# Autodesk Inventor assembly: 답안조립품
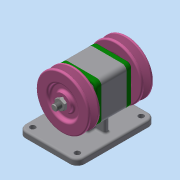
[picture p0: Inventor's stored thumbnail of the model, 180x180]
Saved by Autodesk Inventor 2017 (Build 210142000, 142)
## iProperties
Part Number: 답안조립품
Material: 일반
Document SubType Name: Assembly
Designer: 222
Author: 222
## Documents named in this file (10)
- C:\Users\222\Desktop\701106V1059\답안조립품.iam
- C:\Users\222\Desktop\701106V1059\본체.ipt
- C:\Users\222\Desktop\701106V1059\베어링 6004.ipt
- C:\Users\222\Desktop\701106V1059\축.ipt
- C:\Users\222\Desktop\701106V1059\커버.ipt
- C:\Users\222\Desktop\701106V1059\오일 실 17 30 5.ipt
- C:\Users\222\Desktop\701106V1059\키 5 x 5 x 12.ipt
- C:\Users\222\Desktop\701106V1059\볼트 M4.ipt
- C:\Users\222\Desktop\701106V1059\V-벨트풀리.ipt
- C:\Users\222\Desktop\701106V1059\너트 M10x1.ipt
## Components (2 placed, 1 different names)
1. V-벨트풀리:1
2. V-벨트풀리:2
